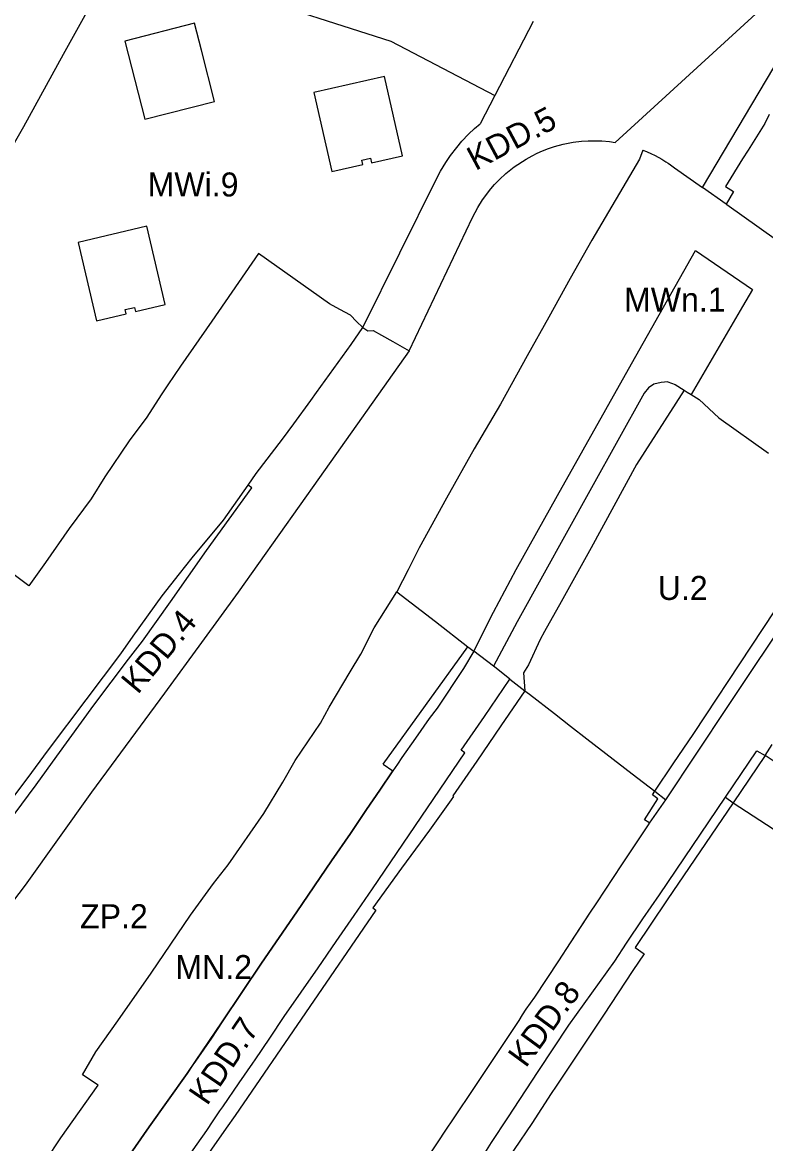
# Model space of a CAD drawing. Extents: x 7425067 to 7426806, y 5549054 to 5550619.
# Drawn here: x 7425501.8 to 7425656.7, y 5549946.2 to 5550179.8 of the extents above; entities that cross this region are included whole.
import ezdxf

# ---------------------------------------------------------------- set-up
doc = ezdxf.new("R2010")
doc.units = 0
for name, color, linetype in [('LIN_Linia Zabudowy Nieprzekraczalna', 7, 'Continuous'), ('LIN_linia zabudowy obowiązująca', 7, 'Continuous'), ('LIN_linie_rozgraniczajace', 7, 'Continuous'), ('TXT_Oznaczenia_przeznaczen', 7, 'Continuous')]:
    doc.layers.add(name, color=color, linetype=linetype)

msp = doc.modelspace()

# ---------------------------------------------------------------- linework, layer by layer
at = {"layer": 'LIN_Linia Zabudowy Nieprzekraczalna'}
for points in [[(7425657.44, 5550160.64), (7425656.55, 5550158.74), (7425653.09, 5550153.21), (7425651.93, 5550151.41), (7425648.38, 5550145.61)], [(7425648.38, 5550145.61), (7425650.0338, 5550144.604)], [(7425650.0338, 5550144.604), (7425648.4681, 5550141.9672)], [(7425595.91, 5550048.79), (7425599.99, 5550056.94), (7425604.69, 5550065.83), (7425613.32, 5550081.22), (7425628.74, 5550108.71), (7425642.1148, 5550132.3368)], [(7425642.1148, 5550132.3368), (7425653.9667, 5550124.1945)], [(7425653.9667, 5550124.1945), (7425651.9, 5550120.66), (7425641.1736, 5550102.3153)], [(7425550.505, 5550085.82), (7425556.01, 5550093.01), (7425558.34, 5550096.2), (7425561.885, 5550101.065), (7425563.1, 5550102.74), (7425566.705, 5550107.725), (7425570.31, 5550112.71), (7425572.76, 5550116.27)], [(7425639.7355, 5550103.2299), (7425629.7884, 5550087.7065)], [(7425629.7884, 5550087.7065), (7425620.3315, 5550070.366), (7425614.139, 5550059.1252), (7425610.6169, 5550052.8992), (7425609.7362, 5550051.2802), (7425607.2604, 5550046.0012), (7425606.2417, 5550044.3093), (7425606.5552, 5550040.5472)], [(7425548.86, 5550083.4), (7425550.505, 5550085.82)], [(7425543.69, 5550076.09), (7425548.86, 5550083.4)], [(7425491.83, 5550007.29), (7425498.3, 5550016.29), (7425502.79, 5550022.22), (7425507.22, 5550028.25), (7425515.07, 5550038.66), (7425522.31, 5550048.28), (7425524.87, 5550051.97), (7425530.95, 5550060.37), (7425534.51, 5550064.9), (7425537.18, 5550068.29), (7425543.69, 5550076.09)], [(7425641.7634, 5550031.6816), (7425665.8055, 5550068.0549)], [(7425577.0224, 5550025.2782), (7425594.6701, 5550049.7458), (7425595.91, 5550048.79)], [(7425606.5552, 5550040.5472), (7425601.53, 5550033.23), (7425596.51, 5550025.92), (7425591.51, 5550018.64), (7425591.6694, 5550018.5304), (7425591.189, 5550017.8631), (7425586.63, 5550011.53), (7425580.79, 5550003.59), (7425574.84, 5549995.3), (7425575.473, 5549994.8457), (7425546.1246, 5549952.0475), (7425544.2494, 5549949.4263), (7425529.4643, 5549928.2635), (7425527.0756, 5549924.5966), (7425526.94, 5549924.69), (7425523.91, 5549920.31), (7425523.42, 5549920.65), (7425520.23, 5549916.11), (7425521.1342, 5549915.4829), (7425511.2359, 5549901.1957), (7425509.48, 5549902.41)], [(7425669.979, 5550041.0643), (7425668.3823, 5550041.0497), (7425659.7796, 5550028.2387), (7425658.2986, 5550025.9526), (7425656.62, 5550027.04)], [(7425633.1513, 5550018.9045), (7425633.6326, 5550019.618), (7425637.4746, 5550025.3135), (7425641.7634, 5550031.6816)], [(7425656.62, 5550027.04), (7425649.98, 5550017.22), (7425636.19, 5549997.03), (7425629.53, 5549987.03), (7425631.4405, 5549985.7401)], [(7425484.89, 5549887.86), (7425484.9072, 5549887.8845), (7425520.8, 5549939.01), (7425528.21, 5549949.7), (7425536.13, 5549960.83), (7425537.865, 5549963.3932), (7425543.4, 5549971.57), (7425551.62, 5549983.77), (7425559, 5549994.51), (7425566.23, 5550005.14), (7425570.21, 5550010.81), (7425573.53, 5550015.83), (7425576.29, 5550019.865), (7425579.04, 5550023.905)], [(7425577.0224, 5550025.2782), (7425579.04, 5550023.905)], [(7425632.5486, 5550012.992), (7425632.4, 5550013.09), (7425631.49, 5550013.69), (7425634.28, 5550018.03), (7425633.1513, 5550018.9045)], [(7425626.76, 5550004.31), (7425632.32, 5550012.66), (7425632.5486, 5550012.992)], [(7425562.96, 5549909.02), (7425568.86, 5549917.69), (7425575.69, 5549927.8), (7425582.5, 5549937.65), (7425585.82, 5549942.63), (7425589.14, 5549947.61), (7425589.3604, 5549947.9398), (7425595.33, 5549956.85), (7425600.34, 5549964.32), (7425605.32, 5549971.85), (7425606.075, 5549973.045), (7425606.83, 5549974.24), (7425608.59, 5549976.71), (7425613.61, 5549984.28), (7425616.08, 5549988.06), (7425618.55, 5549991.84), (7425620.06, 5549994.22), (7425621.56, 5549996.38), (7425626.76, 5550004.31)], [(7425631.4405, 5549985.7401), (7425629.0645, 5549982.3045), (7425622.9208, 5549972.9645), (7425613.0335, 5549958.1687)], [(7425613.0335, 5549958.1687), (7425611.9938, 5549956.6625), (7425607.9586, 5549950.3857)], [(7425607.9586, 5549950.3857), (7425600.624, 5549939.5493), (7425596.9747, 5549934.0514)]]:
    msp.add_lwpolyline(points, dxfattribs=at)
at = {"layer": 'LIN_linia zabudowy obowiązująca'}
for points in [[(7425537.67, 5550179.67), (7425523.14, 5550175.95), (7425527.32, 5550159.65), (7425541.8516, 5550163.3559)], [(7425541.8516, 5550163.3559), (7425539.1, 5550174.07), (7425537.67, 5550179.67)], [(7425572.78, 5550150.2), (7425572.57, 5550151.13), (7425574.38, 5550151.53), (7425574.59, 5550150.6), (7425581, 5550152.05), (7425577.29, 5550168.58), (7425562.57, 5550165.22)], [(7425562.57, 5550165.22), (7425566.27, 5550148.74), (7425572.78, 5550150.2)], [(7425523.41, 5550119.09), (7425523.2, 5550120), (7425525.14, 5550120.46), (7425525.35, 5550119.58), (7425531.56, 5550121.03), (7425527.73, 5550137.35), (7425513.42, 5550133.99), (7425517.25, 5550117.65)], [(7425517.25, 5550117.65), (7425523.41, 5550119.09)]]:
    msp.add_lwpolyline(points, dxfattribs=at)
at = {"layer": 'LIN_linie_rozgraniczajace'}
for points in [[(7425625.3385, 5550154.8249), (7425677.4704, 5550202.5629)], [(7425643.57, 5550145.47), (7425677.4704, 5550202.5629)], [(7425510.365, 5550173.23), (7425518.66, 5550188.28)], [(7425546.82, 5550186.12), (7425578.62, 5550175.9)], [(7425608.28, 5550180), (7425600.2936, 5550164.604)], [(7425578.62, 5550175.9), (7425600.2936, 5550164.604)], [(7425502.07, 5550158.18), (7425510.365, 5550173.23)], [(7425600.2936, 5550164.604), (7425597.2272, 5550158.6926)], [(7425596.0251, 5550157.7026), (7425597.2272, 5550158.6926)], [(7425487.94, 5550133.45), (7425502.07, 5550158.18)], [(7425593.4249, 5550155.08), (7425594.7966, 5550156.5324)], [(7425594.7966, 5550156.5324), (7425596.0251, 5550157.7026)], [(7425592.3323, 5550153.7938), (7425593.4249, 5550155.08)], [(7425612.7209, 5550153.9598), (7425614.5297, 5550154.4473)], [(7425614.5297, 5550154.4473), (7425616.6076, 5550154.8513)], [(7425616.6076, 5550154.8513), (7425618.3669, 5550155.068)], [(7425618.3669, 5550155.068), (7425619.7012, 5550155.1576)], [(7425619.7012, 5550155.1576), (7425620.9085, 5550155.1836)], [(7425620.9085, 5550155.1836), (7425622.5634, 5550155.1347)], [(7425622.5634, 5550155.1347), (7425624.1814, 5550154.9917)], [(7425624.1814, 5550154.9917), (7425625.3385, 5550154.8249)], [(7425590.0734, 5550150.6622), (7425591.0543, 5550152.1125)], [(7425591.0543, 5550152.1125), (7425592.3323, 5550153.7938)], [(7425606.7828, 5550151.3593), (7425608.0317, 5550152.047)], [(7425608.0317, 5550152.047), (7425609.071, 5550152.5583)], [(7425609.071, 5550152.5583), (7425610.2242, 5550153.065)], [(7425610.2242, 5550153.065), (7425611.458, 5550153.5406)], [(7425611.458, 5550153.5406), (7425612.7209, 5550153.9598)], [(7425631.1621, 5550153.2338), (7425630.41, 5550151.31)], [(7425631.1621, 5550153.2338), (7425631.8757, 5550152.9464)], [(7425631.8757, 5550152.9464), (7425632.9073, 5550152.4824)], [(7425632.9073, 5550152.4824), (7425633.5434, 5550152.1708)], [(7425633.5434, 5550152.1708), (7425634.4526, 5550151.6899)], [(7425634.4526, 5550151.6899), (7425635.0875, 5550151.3281)], [(7425588.968, 5550148.8137), (7425590.0734, 5550150.6622)], [(7425602.5995, 5550148.368), (7425604.3317, 5550149.7492)], [(7425604.3317, 5550149.7492), (7425606.7828, 5550151.3593)], [(7425630.41, 5550151.31), (7425620.48, 5550134.48)], [(7425635.0875, 5550151.3281), (7425635.5057, 5550151.0776)], [(7425635.5057, 5550151.0776), (7425635.9573, 5550150.7958)], [(7425635.9573, 5550150.7958), (7425636.4353, 5550150.4843)], [(7425636.4353, 5550150.4843), (7425636.8797, 5550150.1819)], [(7425636.8797, 5550150.1819), (7425637.765, 5550149.5412)], [(7425637.765, 5550149.5412), (7425643.57, 5550145.47)], [(7425572.76, 5550116.27), (7425588.1992, 5550147.3534)], [(7425588.1992, 5550147.3534), (7425588.968, 5550148.8137)], [(7425600.2252, 5550146.0569), (7425601.2256, 5550147.098)], [(7425601.2256, 5550147.098), (7425602.5995, 5550148.368)], [(7425597.7182, 5550142.8747), (7425599.4165, 5550145.1305)], [(7425599.4165, 5550145.1305), (7425600.2252, 5550146.0569)], [(7425648.66, 5550141.83), (7425648.4681, 5550141.9672), (7425643.57, 5550145.47)], [(7425596.7195, 5550141.2865), (7425597.7182, 5550142.8747)], [(7425595.6249, 5550139.2143), (7425596.7195, 5550141.2865)], [(7425662.1, 5550132.23), (7425648.66, 5550141.83)], [(7425582.39, 5550111.4), (7425595.6249, 5550139.2143)], [(7425620.48, 5550134.48), (7425616, 5550126.445)], [(7425550.99, 5550131.67), (7425541.31, 5550117.58)], [(7425565.78, 5550121.18), (7425550.99, 5550131.67)], [(7425616, 5550126.445), (7425611.52, 5550118.41)], [(7425567.98, 5550119.99), (7425565.78, 5550121.18)], [(7425570.18, 5550118.8), (7425567.98, 5550119.99)], [(7425541.31, 5550117.58), (7425534.74, 5550108.21)], [(7425571.47, 5550117.535), (7425570.18, 5550118.8)], [(7425572.76, 5550116.27), (7425571.47, 5550117.535)], [(7425611.52, 5550118.41), (7425607.04, 5550110.375)], [(7425570.31, 5550112.71), (7425572.76, 5550116.27)], [(7425572.76, 5550116.27), (7425573.77, 5550115.56)], [(7425573.77, 5550115.56), (7425574.91, 5550115.67)], [(7425574.91, 5550115.67), (7425576.63, 5550114.69)], [(7425576.63, 5550114.69), (7425578.99, 5550113.35)], [(7425566.705, 5550107.725), (7425570.31, 5550112.71)], [(7425578.99, 5550113.35), (7425582.39, 5550111.4)], [(7425582.39, 5550111.4), (7425563.73, 5550085.01)], [(7425607.04, 5550110.375), (7425601.47, 5550100.32)], [(7425534.74, 5550108.21), (7425532.08, 5550104.29)], [(7425563.1, 5550102.74), (7425566.705, 5550107.725)], [(7425532.08, 5550104.29), (7425530.74, 5550102.21)], [(7425561.885, 5550101.065), (7425563.1, 5550102.74)], [(7425632.29, 5550103.71), (7425631.4, 5550102.57)], [(7425633.44, 5550104.44), (7425632.29, 5550103.71)], [(7425634.93, 5550104.82), (7425633.44, 5550104.44)], [(7425636.33, 5550104.91), (7425634.93, 5550104.82)], [(7425636.33, 5550104.91), (7425637.88, 5550104.41)], [(7425637.88, 5550104.41), (7425639.7355, 5550103.2299), (7425640.38, 5550102.82)], [(7425640.38, 5550102.82), (7425641.1736, 5550102.3153), (7425642.88, 5550101.23)], [(7425530.74, 5550102.21), (7425527.76, 5550097.57)], [(7425558.34, 5550096.2), (7425561.885, 5550101.065)], [(7425601.47, 5550100.32), (7425595.95, 5550090.99)], [(7425631.4, 5550102.57), (7425620.405, 5550082.875)], [(7425642.88, 5550101.23), (7425646.98, 5550097.47)], [(7425527.76, 5550097.57), (7425524.03, 5550092.63)], [(7425556.01, 5550093.01), (7425558.34, 5550096.2)], [(7425646.98, 5550097.47), (7425657.32, 5550090.05)], [(7425524.03, 5550092.63), (7425518.99, 5550085.17)], [(7425550.505, 5550085.82), (7425556.01, 5550093.01)], [(7425595.95, 5550090.99), (7425590.23, 5550080.67)], [(7425518.99, 5550085.17), (7425516.11, 5550080.55)], [(7425563.73, 5550085.01), (7425546.77, 5550061.13)], [(7425548.86, 5550083.4), (7425550.505, 5550085.82)], [(7425544.915, 5550076.35), (7425549.63, 5550082.88)], [(7425549.63, 5550082.88), (7425548.86, 5550083.4)], [(7425620.405, 5550082.875), (7425604.905, 5550054.895)], [(7425516.11, 5550080.55), (7425511.54, 5550074.38)], [(7425590.23, 5550080.67), (7425584.51, 5550070.35)], [(7425540.2, 5550069.82), (7425544.915, 5550076.35)], [(7425511.54, 5550074.38), (7425506.6, 5550067.28)], [(7425584.51, 5550070.35), (7425582.18, 5550065.76)], [(7425536.44, 5550064.465), (7425540.2, 5550069.82)], [(7425503.16, 5550062.43), (7425497.26, 5550066.78)], [(7425506.6, 5550067.28), (7425503.16, 5550062.43)], [(7425582.18, 5550065.76), (7425579.85, 5550061.17)], [(7425532.68, 5550059.11), (7425536.44, 5550064.465)], [(7425546.77, 5550061.13), (7425539.1, 5550050.595)], [(7425575.13, 5550053.65), (7425579.85, 5550061.17)], [(7425579.85, 5550061.17), (7425587.88, 5550054.98)], [(7425529.755, 5550055.02), (7425532.68, 5550059.11)], [(7425648.87, 5550037.28), (7425662.84, 5550058.21)], [(7425526.83, 5550050.93), (7425529.755, 5550055.02)], [(7425572.34, 5550048.22), (7425575.13, 5550053.65)], [(7425587.88, 5550054.98), (7425594.6701, 5550049.7458), (7425595.91, 5550048.79)], [(7425604.905, 5550054.895), (7425599.97, 5550045.7)], [(7425523.88, 5550047.17), (7425526.83, 5550050.93)], [(7425539.1, 5550050.595), (7425531.43, 5550040.06)], [(7425516.67, 5550037.53), (7425523.88, 5550047.17)], [(7425570.09, 5550044.48), (7425572.34, 5550048.22)], [(7425595.91, 5550048.79), (7425593.725, 5550045.215)], [(7425599.97, 5550045.7), (7425595.91, 5550048.79)], [(7425565.73, 5550037.13), (7425570.09, 5550044.48)], [(7425593.725, 5550045.215), (7425588.27, 5550036.97)], [(7425600.1, 5550045.61), (7425599.97, 5550045.7)], [(7425600.23, 5550045.52), (7425600.1, 5550045.61)], [(7425603.4, 5550042.96), (7425600.23, 5550045.52)], [(7425600.755, 5550039.09), (7425603.4, 5550042.96)], [(7425603.4, 5550042.96), (7425606.5552, 5550040.5472), (7425607.48, 5550039.84)], [(7425531.43, 5550040.06), (7425516.18, 5550019.43)], [(7425607.48, 5550039.84), (7425612.68, 5550035.81)], [(7425508.98, 5550026.94), (7425516.67, 5550037.53)], [(7425598.11, 5550035.22), (7425600.755, 5550039.09)], [(7425642.385, 5550027.57), (7425648.87, 5550037.28)], [(7425563.91, 5550033.84), (7425565.73, 5550037.13)], [(7425588.27, 5550036.97), (7425586.6, 5550034.76)], [(7425593.29, 5550028.16), (7425598.11, 5550035.22)], [(7425612.68, 5550035.81), (7425616.08, 5550033.185)], [(7425558.62, 5550026.03), (7425563.91, 5550033.84)], [(7425586.6, 5550034.76), (7425583.755, 5550030.71)], [(7425616.08, 5550033.185), (7425619.48, 5550030.56)], [(7425583.755, 5550030.71), (7425580.91, 5550026.66)], [(7425619.48, 5550030.56), (7425628.9162, 5550023.2747)], [(7425594.05, 5550027.61), (7425593.29, 5550028.16)], [(7425648.3461, 5550018.3616), (7425654.9299, 5550028.0641)], [(7425654.9299, 5550028.0641), (7425656.62, 5550027.04)], [(7425656.62, 5550027.04), (7425658.11, 5550029.34)], [(7425504.63, 5550020.95), (7425508.98, 5550026.94)], [(7425556.07, 5550021.55), (7425558.62, 5550026.03)], [(7425580.91, 5550026.66), (7425579.98, 5550025.28)], [(7425586.23, 5550016.14), (7425594.05, 5550027.61)], [(7425635.9, 5550017.86), (7425642.385, 5550027.57)], [(7425579.98, 5550025.28), (7425579.04, 5550023.905), (7425576.29, 5550019.865)], [(7425628.9162, 5550023.2747), (7425633.6326, 5550019.618), (7425635.9, 5550017.86)], [(7425500.08, 5550014.81), (7425504.63, 5550020.95)], [(7425552.1, 5550014.99), (7425556.07, 5550021.55)], [(7425516.18, 5550019.43), (7425502.33, 5550000.03)], [(7425576.29, 5550019.865), (7425573.53, 5550015.83)], [(7425632.32, 5550012.66), (7425632.5486, 5550012.992), (7425635.9, 5550017.86)], [(7425634.57, 5549998.06), (7425648.3461, 5550018.3616)], [(7425648.3461, 5550018.3616), (7425649.98, 5550017.22)], [(7425649.98, 5550017.22), (7425658.32, 5550011.79)], [(7425544.67, 5550004.28), (7425552.1, 5550014.99)], [(7425573.53, 5550015.83), (7425570.21, 5550010.81)], [(7425578.62, 5550004.9), (7425586.23, 5550016.14)], [(7425626.76, 5550004.31), (7425632.32, 5550012.66)], [(7425570.21, 5550010.81), (7425566.23, 5550005.14)], [(7425566.23, 5550005.14), (7425559, 5549994.51)], [(7425574.79, 5549999.32), (7425578.62, 5550004.9)], [(7425541.61, 5550000.41), (7425544.67, 5550004.28)], [(7425621.56, 5549996.38), (7425626.76, 5550004.31)], [(7425502.33, 5550000.03), (7425487.47, 5549980.59)], [(7425536.81, 5549993.8), (7425541.61, 5550000.41)], [(7425570.96, 5549993.74), (7425574.79, 5549999.32)], [(7425631.15, 5549993.02), (7425634.57, 5549998.06)], [(7425620.06, 5549994.22), (7425621.56, 5549996.38)], [(7425528.66, 5549981.72), (7425536.81, 5549993.8)], [(7425559, 5549994.51), (7425551.62, 5549983.77)], [(7425567.215, 5549988.28), (7425570.96, 5549993.74)], [(7425616.08, 5549988.06), (7425620.06, 5549994.22)], [(7425627.73, 5549987.98), (7425631.15, 5549993.02)], [(7425563.47, 5549982.82), (7425567.215, 5549988.28)], [(7425613.61, 5549984.28), (7425616.08, 5549988.06)], [(7425625.27, 5549984.21), (7425627.73, 5549987.98)], [(7425551.62, 5549983.77), (7425543.4, 5549971.57)], [(7425608.59, 5549976.71), (7425613.61, 5549984.28)], [(7425620.475, 5549977.535), (7425625.27, 5549984.21)], [(7425521.66, 5549971.77), (7425528.66, 5549981.72)], [(7425559.925, 5549977.745), (7425563.47, 5549982.82)], [(7425556.38, 5549972.67), (7425559.925, 5549977.745)], [(7425606.83, 5549974.24), (7425608.59, 5549976.71)], [(7425615.68, 5549970.86), (7425620.475, 5549977.535)], [(7425606.075, 5549973.045), (7425606.83, 5549974.24)], [(7425517.11, 5549965.3), (7425521.66, 5549971.77)], [(7425553.36, 5549968.18), (7425556.38, 5549972.67)], [(7425600.34, 5549964.32), (7425605.32, 5549971.85)], [(7425605.32, 5549971.85), (7425606.075, 5549973.045)], [(7425543.4, 5549971.57), (7425541.21, 5549968.14)], [(7425609.335, 5549961.23), (7425615.68, 5549970.86)], [(7425541.21, 5549968.14), (7425538.51, 5549964.28)], [(7425550.34, 5549963.69), (7425553.36, 5549968.18)], [(7425514.31, 5549960.5), (7425517.11, 5549965.3)], [(7425537.31, 5549962.63), (7425536.13, 5549960.83)], [(7425538.51, 5549964.28), (7425537.865, 5549963.3932), (7425537.31, 5549962.63)], [(7425546.98, 5549958.83), (7425549.84, 5549962.94)], [(7425549.84, 5549962.94), (7425550.34, 5549963.69)], [(7425595.33, 5549956.85), (7425600.34, 5549964.32)], [(7425517.59, 5549958.38), (7425514.31, 5549960.5)], [(7425536.13, 5549960.83), (7425528.21, 5549949.7)], [(7425602.99, 5549951.6), (7425609.335, 5549961.23)], [(7425509.79, 5549947.39), (7425517.59, 5549958.38)], [(7425543.54, 5549953.84), (7425546.98, 5549958.83)], [(7425589.14, 5549947.61), (7425589.3604, 5549947.9398), (7425595.33, 5549956.85)], [(7425542.94, 5549953.01), (7425543.54, 5549953.84)], [(7425540.21, 5549948.92), (7425541.575, 5549950.965)], [(7425541.575, 5549950.965), (7425542.94, 5549953.01)], [(7425599.57, 5549946.4), (7425602.99, 5549951.6)], [(7425528.21, 5549949.7), (7425520.8, 5549939.01)], [(7425536.19, 5549943.2), (7425540.21, 5549948.92)], [(7425503.53, 5549937.93), (7425509.79, 5549947.39)], [(7425585.82, 5549942.63), (7425589.14, 5549947.61)], [(7425593.35, 5549936.43), (7425599.57, 5549946.4)]]:
    msp.add_lwpolyline(points, dxfattribs=at)

# ---------------------------------------------------------------- texts
at = {"layer": 'TXT_Oznaczenia_przeznaczen'}
for s, rotation, p in [('KDD.5', 28.158719, (7425596.2393, 5550148.847)), ('KDD.4', 50.209057, (7425525.8335, 5550039.6453)), ('KDD.8', 53.760346, (7425606.7224, 5549961.8104)), ('KDD.7', 55.748217, (7425540.2907, 5549953.9305))]:
    msp.add_text(s, height=5, rotation=rotation, dxfattribs=at).set_placement(p)
for s, p in [('MWi.9', (7425527.9024, 5550143.5647)), ('MWn.1', (7425627.2168, 5550119.5689)), ('U.2', (7425634.2406, 5550059.4909)), ('ZP.2', (7425513.806, 5549991.0845)), ('MN.2', (7425533.6858, 5549980.4833))]:
    msp.add_text(s, height=5, dxfattribs=at).set_placement(p)

doc.saveas('drawing.dxf')
